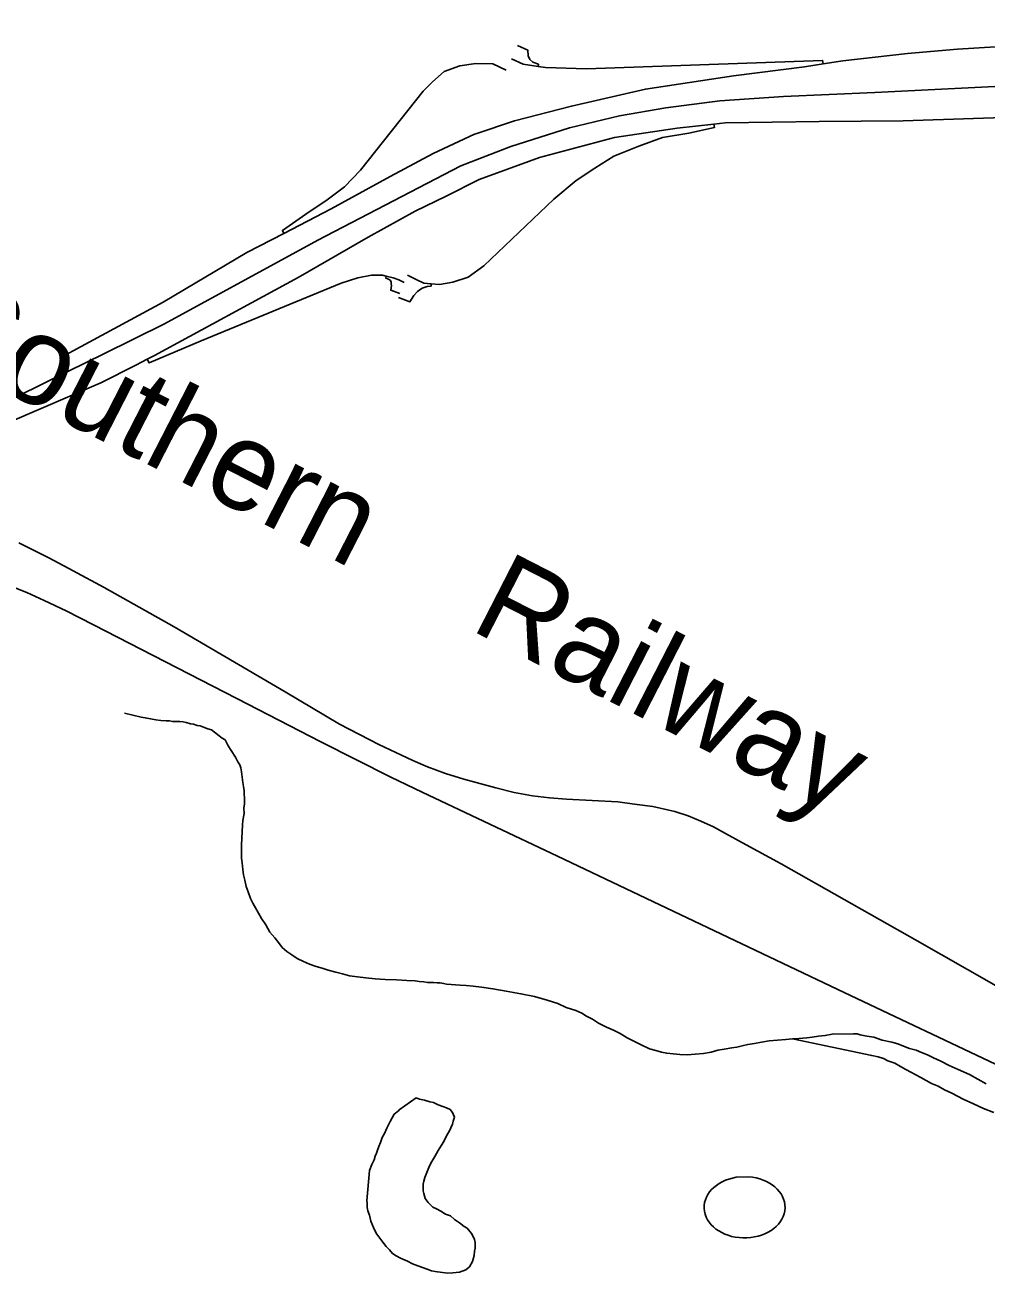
# Model space of a CAD drawing. Extents: x 0 to 96.2, y -27.5 to 31.3.
# Drawn here: x 44.702 to 45.317, y 15.122 to 15.92 of the extents above; entities that cross this region are included whole.
import ezdxf

# ---------------------------------------------------------------- set-up
doc = ezdxf.new("R2010")
doc.units = 0
for name, color, linetype in [('TB_BORDER', 7, 'Continuous'), ('TB_PP_50x10_GRID', 7, 'Continuous'), ('TB_PROF_20x5', 7, 'Continuous'), ('TB_PROF_20x5_GRID', 7, 'Continuous'), ('TB_PSNSUM', 7, 'Continuous'), ('TB_UNDERDRAIN', 7, 'Continuous')]:
    doc.layers.add(name, color=color, linetype=linetype)

msp = doc.modelspace()

# ---------------------------------------------------------------- linework, layer by layer
at = {"layer": 'TB_BORDER'}
for points in [[(44.7658, 15.47991), (44.77647, 15.47737), (44.77913, 15.47703), (44.78256, 15.47631), (44.78598, 15.47559), (44.78903, 15.47525), (44.79245, 15.47491), (44.79473, 15.47494), (44.79663, 15.47458), (44.79891, 15.47461), (44.80119, 15.47463), (44.80347, 15.47428), (44.80537, 15.47392), (44.80804, 15.4732), (44.80994, 15.47284), (44.81223, 15.47211), (44.81414, 15.47175), (44.81642, 15.47102), (44.8191, 15.46991), (44.82139, 15.46918), (44.8233, 15.46768), (44.82637, 15.46544), (44.82829, 15.46394), (44.83021, 15.46282), (44.83216, 15.45905), (44.8341, 15.45603), (44.83681, 15.45188), (44.83837, 15.44886), (44.83954, 15.44697), (44.84032, 15.44508), (44.84074, 15.44243), (44.84117, 15.43901), (44.84159, 15.4356), (44.84201, 15.43294), (44.84242, 15.43029), (44.84245, 15.42839), (44.84249, 15.42535), (44.84254, 15.42193), (44.8422, 15.41926), (44.84225, 15.41584), (44.84155, 15.41128), (44.84121, 15.40823), (44.84062, 15.39568), (44.84065, 15.3934), (44.84069, 15.39074), (44.84074, 15.38732), (44.84116, 15.38429), (44.8416, 15.38011), (44.84203, 15.3767), (44.84283, 15.37329), (44.84365, 15.36911), (44.84483, 15.36571), (44.84641, 15.36155), (44.84797, 15.35853), (44.84953, 15.35551), (44.85148, 15.35211), (44.85342, 15.34871), (44.85614, 15.34457), (44.85886, 15.34004), (44.86195, 15.33627), (44.86427, 15.33326), (44.86659, 15.33025), (44.86966, 15.32763), (44.87273, 15.32538), (44.87618, 15.32315), (44.88038, 15.3213), (44.8842, 15.31944), (44.8884, 15.31797), (44.89221, 15.31688), (44.89602, 15.31578), (44.90098, 15.31433), (44.90517, 15.31323), (44.90974, 15.31215), (44.91469, 15.31145), (44.92001, 15.31075), (44.9261, 15.31007), (44.93256, 15.30976), (44.93977, 15.30947), (44.94623, 15.30917), (44.95155, 15.30885), (44.95421, 15.30851), (44.95726, 15.30816), (44.95954, 15.30781), (44.96334, 15.30786), (44.96562, 15.3075), (44.96752, 15.30753), (44.9698, 15.30718), (44.97171, 15.30682), (44.98045, 15.30616), (44.98425, 15.30583), (44.98881, 15.3055), (44.99414, 15.30481), (45.00136, 15.30375), (45.00974, 15.30234), (45.01925, 15.30055), (45.02801, 15.29876), (45.03601, 15.29658), (45.04288, 15.29438), (45.04823, 15.29178), (45.05433, 15.28996), (45.05815, 15.2881)], [(45.05815, 15.2881), (45.06121, 15.28624), (45.06504, 15.28438), (45.06887, 15.28177), (45.07384, 15.27917), (45.07842, 15.27733), (45.08263, 15.2751), (45.08722, 15.27249), (45.09143, 15.27026), (45.09602, 15.26804), (45.10137, 15.26544), (45.10556, 15.26435), (45.109, 15.26325), (45.11242, 15.26253), (45.1166, 15.26221), (45.12078, 15.26188), (45.12573, 15.26156), (45.13065, 15.262), (45.13596, 15.26244), (45.14089, 15.26326), (45.14505, 15.26445), (45.14921, 15.26526), (45.15414, 15.26608), (45.15717, 15.2665), (45.16058, 15.2673), (45.16436, 15.2681), (45.16853, 15.26891), (45.17307, 15.26973), (45.178, 15.27055), (45.18331, 15.27099), (45.18862, 15.27144), (45.19279, 15.27187), (45.19696, 15.27192), (45.20189, 15.27236), (45.20531, 15.27278), (45.20947, 15.27359), (45.21364, 15.27402), (45.21819, 15.27483), (45.23185, 15.275), (45.23413, 15.27503), (45.23604, 15.27429), (45.24023, 15.27358), (45.24479, 15.27288), (45.25013, 15.27104), (45.25623, 15.26959), (45.26004, 15.2685), (45.26386, 15.26703), (45.26767, 15.26555), (45.27187, 15.26446), (45.2753, 15.26299), (45.27912, 15.26151), (45.28294, 15.25966), (45.28753, 15.25743), (45.29288, 15.25484), (45.29861, 15.25225), (45.30587, 15.24891), (45.31123, 15.24594), (45.31659, 15.24296)], [(45.19279, 15.27187), (45.24344, 15.26108), (45.24762, 15.26037), (45.25105, 15.25927), (45.25373, 15.25778), (45.25831, 15.25632), (45.26176, 15.25408), (45.2652, 15.25222), (45.27477, 15.24702), (45.27821, 15.24516), (45.28165, 15.2433), (45.28585, 15.24145), (45.29006, 15.23922), (45.29465, 15.237), (45.30191, 15.23328), (45.30841, 15.23032), (45.3149, 15.22736), (45.32139, 15.22478)]]:
    msp.add_lwpolyline(points, dxfattribs=at)
at = {"layer": 'TB_PP_50x10_GRID'}
for points in [[(44.69838, 15.58882), (44.71746, 15.57919), (44.73314, 15.57097), (44.75279, 15.5602), (44.79757, 15.53498), (44.8686, 15.49351), (44.90336, 15.47282), (44.92849, 15.45979), (44.95012, 15.44959), (44.95947, 15.44553), (44.97099, 15.44127), (44.98271, 15.43769), (45.0033, 15.43211), (45.01482, 15.42928), (45.02654, 15.42711), (45.03749, 15.42578), (45.04845, 15.42493), (45.08113, 15.42333), (45.09181, 15.42182), (45.10362, 15.42021), (45.1176, 15.417), (45.1261, 15.41426), (45.13432, 15.41095), (45.14234, 15.40717), (45.15, 15.40311), (45.16322, 15.39574), (45.18561, 15.38356), (45.271, 15.33529), (45.49421, 15.20815)], [(44.69323, 15.56102), (44.70334, 15.55702), (44.71445, 15.55191), (44.72855, 15.54529), (44.74614, 15.53631), (44.83761, 15.48926), (44.8914, 15.46168), (44.93607, 15.43897), (44.95604, 15.42945), (45.04256, 15.38852), (45.2258, 15.30148), (45.32665, 15.25358)]]:
    msp.add_lwpolyline(points, dxfattribs=at)
at = {"layer": 'TB_PROF_20x5_GRID'}
for points in [[(45.32247, 15.9057), (45.29836, 15.90428), (45.26621, 15.90144), (45.22507, 15.89671), (45.21242, 15.89477), (45.20048, 15.89293), (45.15509, 15.88726), (45.09882, 15.87874), (45.05154, 15.86786), (45.01513, 15.8584), (44.99044, 15.85017), (44.98959, 15.84989), (44.96311, 15.83758), (44.93569, 15.82293), (44.89786, 15.80211), (44.8678, 15.78654), (44.84396, 15.7742), (44.79053, 15.74251), (44.7381, 15.71419), (44.72557, 15.70742), (44.73011, 15.69846)], [(45.03016, 15.89318), (45.03037, 15.89459), (45.02682, 15.89604), (45.02489, 15.89766), (45.02392, 15.89991), (45.0236, 15.90362), (45.0171, 15.90664)], [(45.21242, 15.89477), (45.21207, 15.89704), (45.06122, 15.89177), (45.03487, 15.89248), (45.03016, 15.89318), (45.02063, 15.8946), (45.01312, 15.89809)], [(45.00976, 15.89087), (45.00122, 15.89484), (44.99039, 15.89507), (44.98028, 15.89366), (44.97016, 15.88989), (44.96263, 15.8833), (44.95675, 15.87742), (44.91675, 15.82681), (44.90639, 15.81621), (44.89463, 15.80727), (44.8838, 15.80021), (44.86683, 15.78841), (44.8678, 15.78654)], [(44.65291, 15.64911), (44.75074, 15.691), (44.77308, 15.70232), (44.78046, 15.70606), (44.78509, 15.70841), (44.87683, 15.7583), (44.92152, 15.78418), (44.95163, 15.80065), (44.97136, 15.8104), (44.99256, 15.82089), (45.03114, 15.835), (45.07912, 15.84771), (45.11911, 15.85383), (45.14263, 15.85637), (45.14969, 15.85713), (45.20991, 15.85807), (45.26354, 15.85854), (45.48183, 15.86559)], [(44.94677, 15.75975), (44.95231, 15.75705), (44.95729, 15.75478), (44.96193, 15.75422), (44.9671, 15.75384), (44.97581, 15.75526), (44.98545, 15.75855), (44.99558, 15.76585), (45.04028, 15.80845), (45.05464, 15.82022), (45.0664, 15.82823), (45.07863, 15.83576), (45.09463, 15.84234), (45.1097, 15.84776), (45.12663, 15.85058), (45.14287, 15.85411), (45.14263, 15.85637)], [(44.78046, 15.70606), (44.78163, 15.70375), (44.81486, 15.71783), (44.90428, 15.75479), (44.9151, 15.75809), (44.92381, 15.75973), (44.93087, 15.75973), (44.93313, 15.75925), (44.93761, 15.75816), (44.94121, 15.75683), (44.94456, 15.7552)], [(44.93313, 15.75925), (44.93285, 15.75793), (44.93461, 15.75725), (44.9353, 15.7569), (44.93586, 15.75632), (44.93623, 15.75529), (44.93638, 15.75431), (44.93643, 15.75322), (44.93605, 15.75021), (44.94184, 15.74809)], [(44.94091, 15.74555), (44.94828, 15.74286), (44.95073, 15.74682), (44.95318, 15.74945), (44.95619, 15.75152), (44.95939, 15.75265), (44.96183, 15.75284), (44.96193, 15.75422)]]:
    msp.add_lwpolyline(points, dxfattribs=at)
at = {"layer": 'TB_PSNSUM'}
for points in [[(44.73011, 15.69846), (44.75228, 15.70938), (44.79139, 15.72863), (44.88943, 15.78226), (44.98073, 15.8297), (45.01286, 15.84195), (45.05028, 15.85388), (45.08223, 15.86163), (45.11191, 15.86679), (45.14643, 15.87131), (45.18708, 15.87389), (45.24535, 15.87648), (45.5604, 15.8923), (45.6224, 15.90192), (45.68762, 15.91811), (45.692, 15.91971)], [(44.63134, 15.65173), (44.68103, 15.6743), (44.73011, 15.69846)]]:
    msp.add_lwpolyline(points, dxfattribs=at)
at = {"layer": 'TB_UNDERDRAIN'}
for points in [[(44.94132, 15.22648), (44.95221, 15.23399), (44.9545, 15.23326), (44.95754, 15.23254), (44.96097, 15.23144), (44.96326, 15.23109), (44.96632, 15.2296), (44.96937, 15.2285), (44.97166, 15.22777), (44.97395, 15.22665), (44.9755, 15.22478), (44.97668, 15.22175), (44.97595, 15.21908), (44.9756, 15.21718), (44.97449, 15.21488), (44.97338, 15.21259), (44.9719, 15.21029), (44.97006, 15.20609), (44.96857, 15.20379), (44.96634, 15.20034), (44.96411, 15.19651), (44.96226, 15.19345), (44.96115, 15.19154), (44.96041, 15.18963), (44.95785, 15.18314), (44.95712, 15.18085), (44.95676, 15.17894), (44.95679, 15.17704), (44.95682, 15.17476), (44.95723, 15.17287), (44.95803, 15.16984), (44.95996, 15.1672), (44.96304, 15.1642), (44.96534, 15.16308), (44.96801, 15.1616), (44.97108, 15.15973), (44.97413, 15.15863), (44.97682, 15.15638), (44.97989, 15.15414), (44.98296, 15.1519), (44.98487, 15.15078), (44.98757, 15.14739), (44.98874, 15.1455), (44.98952, 15.14361), (44.98993, 15.14172), (44.98996, 15.13982), (44.98998, 15.13792), (44.98963, 15.13601), (44.98929, 15.13335), (44.9882, 15.12954), (44.98635, 15.12609), (44.9841, 15.12417), (44.97994, 15.12259), (44.97577, 15.12217), (44.97235, 15.12212), (44.96437, 15.12317), (44.96209, 15.12352), (44.95941, 15.12463), (44.95636, 15.12573), (44.95331, 15.12683), (44.94988, 15.12793), (44.94681, 15.12979), (44.94223, 15.13164), (44.93955, 15.13313), (44.93725, 15.13462), (44.93532, 15.13688), (44.93301, 15.13913), (44.93108, 15.14177), (44.92914, 15.1444), (44.92721, 15.14704), (44.92565, 15.14968), (44.92447, 15.15271), (44.9233, 15.15535), (44.92248, 15.15915), (44.92131, 15.16179), (44.9209, 15.16407), (44.92086, 15.16673), (44.92084, 15.16836)], [(44.92084, 15.16836), (44.92247, 15.18765), (44.92394, 15.19147), (44.92541, 15.19452), (44.92614, 15.19681), (44.92687, 15.19872), (44.92761, 15.20063), (44.92833, 15.20292), (44.92944, 15.20559), (44.93053, 15.20865), (44.93202, 15.21133), (44.93349, 15.21476), (44.93571, 15.21897), (44.9383, 15.22356), (44.94093, 15.22588), (44.94132, 15.22648)], [(45.16467, 15.18362), (45.1569, 15.18329)]]:
    msp.add_lwpolyline(points, dxfattribs=at)
msp.add_ellipse((45.16219, 15.16414), major_axis=(0.02588, 0.0001), ratio=0.756188, start_param=1.773386, end_param=7.754901, dxfattribs=at)

# ---------------------------------------------------------------- texts
at = {"layer": 'TB_PROF_20x5'}
msp.add_text('Norfolk    Southern    Railway', height=0.0566288, rotation=332.84934, dxfattribs=at).set_placement((44.34891, 15.86028))

doc.saveas('drawing.dxf')
